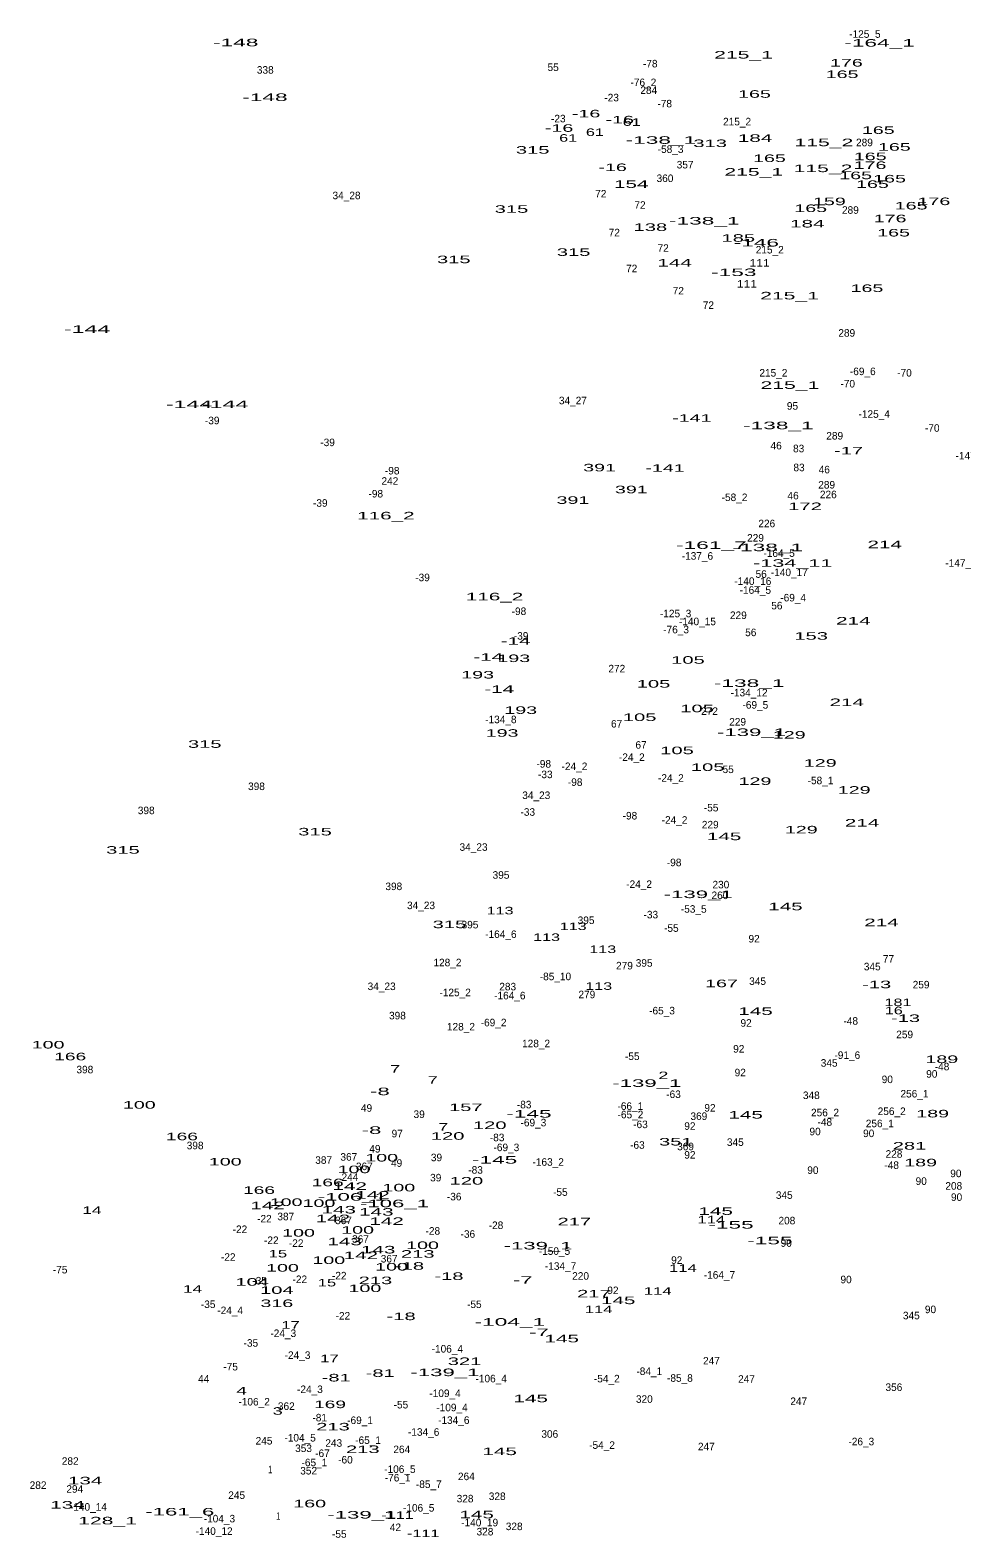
# Model space of a CAD drawing. Extents: x -662499 to -659675, y -1001682 to -998165.
# Drawn here: x -661282 to -660787, y -999947 to -999147 of the extents above; entities that cross this region are included whole.
import ezdxf
from ezdxf.enums import TextEntityAlignment as Align

# ---------------------------------------------------------------- set-up
doc = ezdxf.new("R2010")
doc.units = 0
doc.header["$LTSCALE"] = 1.6
doc.layers.add('24', color=7, linetype='Continuous')

msp = doc.modelspace()

# ---------------------------------------------------------------- texts
at = {"layer": '24'}
for s, p in [('-125_5', (-660838.646, -999150.64)), ('-78', (-660952.591, -999166.37)), ('338', (-661156.977, -999169.7)), ('55', (-661004.147, -999168.29)), ('-76_2', (-660956.234, -999176.31)), ('284', (-660953.381, -999180.47)), ('-23', (-660973.105, -999184.39)), ('-78', (-660944.931, -999187.61)), ('-23', (-661001.405, -999195.54)), ('215_2', (-660906.499, -999197.15)), ('-58_3', (-660941.792, -999211.8)), ('289', (-660838.873, -999208.24)), ('357', (-660934.083, -999220.04)), ('360', (-660944.767, -999227.26)), ('34_28', (-661113.83, -999236.38)), ('72', (-660978.853, -999235.47)), ('72', (-660958.043, -999241.48)), ('289', (-660846.343, -999244.12)), ('72', (-660971.693, -999256.1)), ('72', (-660945.743, -999264.33)), ('215_2', (-660889.149, -999265.21)), ('72', (-660962.443, -999275.17)), ('72', (-660937.703, -999287)), ('72', (-660921.733, -999294.65)), ('289', (-660848.283, -999309.41)), ('215_2', (-660887.209, -999330.6)), ('-69_6', (-660839.768, -999329.84)), ('-70', (-660817.614, -999330.58)), ('-70', (-660847.754, -999336.4)), ('34_27', (-660993.655, -999345.31)), ('95', (-660877.093, -999348.19)), ('-39', (-661185.15, -999355.93)), ('-125_4', (-660833.68, -999352.5)), ('289', (-660854.673, -999364.04)), ('-70', (-660802.874, -999359.93)), ('-39', (-661123.89, -999367.56)), ('46', (-660885.767, -999369.29)), ('83', (-660873.807, -999370.81)), ('-147_2', (-660782.176, -999374.64)), ('-98', (-661089.59, -999382.6)), ('83', (-660873.607, -999380.88)), ('46', (-660860.207, -999381.99)), ('242', (-661090.821, -999388.08)), ('289', (-660858.943, -999390.07)), ('-98', (-661098.31, -999394.82)), ('-58_2', (-660907.842, -999396.74)), ('46', (-660876.767, -999395.84)), ('226', (-660858.063, -999395.23)), ('-39', (-661127.77, -999399.76)), ('226', (-660890.723, -999410.65)), ('229', (-660896.713, -999418.28)), ('-137_6', (-660927.547, -999427.88)), ('-164_5', (-660884.196, -999426.4)), ('56', (-660893.703, -999437.51)), ('-140_17', (-660878.753, -999436.59)), ('-147_2', (-660787.606, -999431.65)), ('-39', (-661073.48, -999439.32)), ('-140_16', (-660898.133, -999441.28)), ('-164_5', (-660896.806, -999445.99)), ('56', (-660885.373, -999454.27)), ('-69_4', (-660876.718, -999450.05)), ('-98', (-661022.31, -999457.27)), ('-125_3', (-660939.126, -999458.47)), ('-140_15', (-660927.537, -999462.69)), ('229', (-660905.823, -999459.39)), ('-39', (-661021.14, -999470.35)), ('-76_3', (-660938.874, -999466.98)), ('56', (-660899.223, -999468.5)), ('272', (-660970.353, -999487.74)), ('-134_12', (-660900.123, -999500.47)), ('272', (-660921.133, -999510.34)), ('-69_5', (-660896.793, -999507)), ('-134_8', (-661031.9, -999514.73)), ('67', (-660970.448, -999517.03)), ('229', (-660906.213, -999515.99)), ('-24_2', (-660962.387, -999534.79)), ('67', (-660957.478, -999528.26)), ('-98', (-661009.13, -999538.33)), ('-24_2', (-660992.827, -999539.64)), ('-55', (-660912.115, -999541.24)), ('398', (-661161.643, -999550.26)), ('-33', (-661008.315, -999543.93)), ('-98', (-660992.46, -999548.03)), ('-24_2', (-660941.647, -999545.84)), ('-58_1', (-660862.196, -999547.15)), ('34_23', (-661013.1, -999555.01)), ('398', (-661220.183, -999563.06)), ('-33', (-661017.615, -999563.91)), ('-98', (-660963.38, -999565.87)), ('-55', (-660920.265, -999561.6)), ('-24_2', (-660939.707, -999568.15)), ('229', (-660920.753, -999570.63)), ('34_23', (-661046.4, -999582.52)), ('-98', (-660939.92, -999590.7)), ('395', (-661031.833, -999597.36)), ('398', (-661088.743, -999603.4)), ('-24_2', (-660958.517, -999602.26)), ('230', (-660915.101, -999602.48)), ('34_23', (-661074.28, -999613.51)), ('260', (-660915.607, -999608.16)), ('395', (-660986.653, -999621.41)), ('-33', (-660952.285, -999618.41)), ('-53_5', (-660929.502, -999615.42)), ('395', (-661048.303, -999623.74)), ('-164_6', (-661031.901, -999628.82)), ('-55', (-660941.395, -999625.56)), ('92', (-660897.463, -999631.22)), ('128_2', (-661060.259, -999643.87)), ('279', (-660966.288, -999645.52)), ('395', (-660955.833, -999644.1)), ('345', (-660834.741, -999646.01)), ('77', (-660826.149, -999641.95)), ('-85_10', (-661002.92, -999651.27)), ('345', (-660895.611, -999653.76)), ('34_23', (-661095.2, -999656.51)), ('-125_2', (-661056.176, -999659.76)), ('-164_6', (-661027.151, -999661.4)), ('283', (-661028.267, -999656.66)), ('279', (-660986.248, -999660.84)), ('259', (-660808.803, -999655.61)), ('-65_3', (-660946.348, -999669.42)), ('398', (-661086.803, -999672.05)), ('128_2', (-661053.099, -999677.96)), ('-69_2', (-661035.753, -999675.75)), ('92', (-660901.723, -999675.97)), ('-48', (-660846.149, -999674.9)), ('128_2', (-661013.209, -999686.87)), ('259', (-660817.533, -999682.08)), ('-55', (-660962.135, -999693.66)), ('92', (-660905.593, -999689.72)), ('-91_6', (-660847.967, -999693.07)), ('398', (-661252.753, -999700.72)), ('92', (-660904.823, -999702.31)), ('345', (-660857.621, -999697.21)), ('90', (-660803.127, -999703.03)), ('-48', (-660797.689, -999699.14)), ('90', (-660826.747, -999705.93)), ('-83', (-661019.545, -999719.33)), ('-63', (-660940.24, -999713.84)), ('348', (-660867.081, -999714.39)), ('256_1', (-660812.314, -999713.56)), ('49', (-661103.227, -999721.14)), ('39', (-661075.283, -999724.45)), ('-66_1', (-660963.157, -999720.15)), ('-65_2', (-660963.108, -999724.61)), ('369', (-660926.788, -999725.5)), ('92', (-660920.893, -999721.05)), ('256_2', (-660859.8, -999723.55)), ('256_2', (-660824.42, -999722.87)), ('97', (-661086.928, -999734.72)), ('-69_3', (-661014.623, -999728.89)), ('-63', (-660957.78, -999729.84)), ('92', (-660931.543, -999730.73)), ('90', (-660865.087, -999733.63)), ('-48', (-660859.919, -999728.62)), ('90', (-660836.627, -999734.6)), ('256_1', (-660830.734, -999729.36)), ('398', (-661194.213, -999741.06)), ('49', (-661098.777, -999742.83)), ('-83', (-661033.895, -999736.79)), ('-69_3', (-661028.963, -999742.07)), ('-63', (-660959.43, -999740.8)), ('369', (-660933.858, -999741.6)), ('345', (-660907.441, -999739.28)), ('387', (-661125.983, -999748.8)), ('367', (-661112.628, -999747.12)), ('49', (-661087.247, -999750.38)), ('39', (-661066.083, -999747.41)), ('-163_2', (-661006.792, -999749.83)), ('92', (-660931.543, -999746.04)), ('228', (-660823.187, -999745.57)), ('244', (-661112.026, -999757.84)), ('367', (-661104.388, -999752.15)), ('39', (-661066.473, -999758.14)), ('-83', (-661045.325, -999754.05)), ('90', (-660866.247, -999754.17)), ('-48', (-660824.439, -999751.51)), ('90', (-660790.347, -999755.91)), ('-55', (-661000.325, -999765.81)), ('345', (-660881.461, -999767.4)), ('90', (-660808.737, -999759.98)), ('208', (-660791.461, -999762.53)), ('-36', (-661056.69, -999768.21)), ('90', (-660789.957, -999768.5)), ('-22', (-661157.445, -999779.95)), ('387', (-661146.093, -999778.77)), ('367', (-661115.438, -999780.85)), ('-28', (-661034.485, -999783.43)), ('208', (-660880.051, -999780.96)), ('-22', (-661170.435, -999785.57)), ('-22', (-661153.765, -999791.39)), ('367', (-661106.428, -999790.74)), ('-28', (-661068.025, -999786.44)), ('-36', (-661049.42, -999788.09)), ('-22', (-661140.575, -999792.94)), ('-150_5', (-661003.43, -999797.15)), ('90', (-660880.387, -999792.88)), ('-75', (-661265.871, -999807.03)), ('-22', (-661176.635, -999800.31)), ('367', (-661091.208, -999801.21)), ('-134_7', (-661000.206, -999805.1)), ('92', (-660938.513, -999801.94)), ('-35', (-661159.975, -999812.89)), ('-22', (-661138.635, -999812.14)), ('-22', (-661117.705, -999810.2)), ('220', (-660989.571, -999810.36)), ('-164_7', (-660915.852, -999809.8)), ('90', (-660848.627, -999812.25)), ('92', (-660972.403, -999818.01)), ('-35', (-661187.305, -999825.4)), ('-24_4', (-661175.601, -999828.65)), ('-22', (-661115.765, -999831.53)), ('-55', (-661045.985, -999825.41)), ('345', (-660814.001, -999831.38)), ('90', (-660803.817, -999828.13)), ('-35', (-661164.625, -999845.96)), ('-24_3', (-661147.417, -999840.8)), ('-24_3', (-661139.857, -999852.43)), ('-106_4', (-661060.31, -999849.07)), ('247', (-660920.107, -999855.4)), ('-75', (-661175.371, -999858.56)), ('-84_1', (-660953.11, -999860.98)), ('44', (-661189.646, -999864.99)), ('-24_3', (-661133.267, -999870.57)), ('-106_4', (-661037.04, -999864.87)), ('-54_2', (-660975.667, -999864.91)), ('-85_8', (-660936.842, -999864.58)), ('247', (-660901.497, -999865.1)), ('356', (-660823.253, -999869.45)), ('-106_2', (-661162.896, -999877.18)), ('362', (-661145.813, -999879.53)), ('-55', (-661084.955, -999878.74)), ('-109_4', (-661061.53, -999872.68)), ('320', (-660955.741, -999875.75)), ('247', (-660873.767, -999876.93)), ('-81', (-661128.071, -999885.63)), ('-69_1', (-661106.657, -999887.02)), ('-109_4', (-661057.84, -999880.25)), ('-134_6', (-661056.906, -999886.96)), ('-134_6', (-661072.896, -999893.26)), ('306', (-661005.937, -999894.32)), ('245', (-661157.631, -999897.92)), ('-104_5', (-661138.484, -999896.33)), ('353', (-661136.657, -999901.9)), ('243', (-661120.631, -999899.11)), ('-65_1', (-661102.392, -999897.61)), ('264', (-661084.527, -999902.49)), ('-54_2', (-660978.187, -999900.21)), ('247', (-660922.817, -999900.98)), ('-26_3', (-660840.538, -999898.32)), ('282', (-661260.537, -999908.7)), ('-65_1', (-661130.882, -999909.44)), ('-67', (-661126.615, -999904.55)), ('-60', (-661114.414, -999908)), ('352', (-661133.947, -999913.83)), ('-106_5', (-661085.516, -999913.01)), ('-76_1', (-661086.697, -999917.54)), ('264', (-661050.217, -999916.84)), ('282', (-661277.597, -999921.5)), ('294', (-661258.117, -999923.53)), ('245', (-661172.171, -999926.82)), ('-85_7', (-661070.158, -999921.01)), ('328', (-661033.837, -999927.39)), ('-140_14', (-661250.851, -999933.05)), ('-106_5', (-661075.526, -999933.54)), ('328', (-661050.897, -999928.65)), ('-104_3', (-661181.324, -999939.28)), ('-140_19', (-661043.153, -999941.35)), ('328', (-661024.827, -999943.39)), ('-140_12', (-661184.127, -999945.9)), ('-55', (-661117.675, -999947.43)), ('42', (-661087.881, -999943.9)), ('328', (-661040.337, -999946.21))]:
    msp.add_text(s, height=4, dxfattribs=at).set_placement(p, align=Align.CENTER)
for s, width, p in [('-148', 2.25, (-661172.666, -999155.13)), ('-164_1', 2.25, (-660830.858, -999155.34)), ('215_1', 2.1, (-660903.065, -999161.66)), ('176', 1.95, (-660848.467, -999165.91)), ('165', 1.95, (-660850.733, -999172.01)), ('165', 1.95, (-660897.253, -999182.49)), ('-148', 2.25, (-661157.166, -999184.22)), ('-16', 1.95, (-660986.625, -999192.92)), ('-16', 1.95, (-660968.785, -999196.12)), ('61', 1.6, (-660962.433, -999197.41)), ('-16', 1.95, (-661000.965, -999200.58)), ('61', 1.6, (-660996.173, -999205.84)), ('61', 1.6, (-660981.983, -999202.79)), ('184', 2.05, (-660896.953, -999205.91)), ('165', 1.95, (-660831.533, -999201.69)), ('315', 2, (-661015.007, -999212.19)), ('-138_1', 2.25, (-660946.957, -999206.95)), ('313', 2, (-660920.807, -999208.68)), ('115_2', 2.1, (-660860.405, -999208.23)), ('165', 1.95, (-660823.003, -999210.61)), ('-16', 1.95, (-660972.565, -999221.43)), ('165', 1.95, (-660889.313, -999216.62)), ('115_2', 2.1, (-660860.885, -999221.99)), ('176', 1.95, (-660835.917, -999220.31)), ('165', 1.95, (-660835.803, -999215.65)), ('154', 2.05, (-660962.703, -999230.37)), ('215_1', 2.1, (-660897.635, -999223.87)), ('165', 1.95, (-660843.553, -999225.74)), ('165', 1.95, (-660834.633, -999230.39)), ('165', 1.95, (-660825.533, -999227.48)), ('315', 2, (-661026.257, -999243.6)), ('165', 1.95, (-660867.403, -999243.19)), ('159', 1.95, (-660857.493, -999239.55)), ('165', 1.95, (-660814.083, -999241.83)), ('176', 1.95, (-660801.997, -999239.51)), ('138', 2, (-660952.527, -999253.23)), ('-138_1', 2.25, (-660923.927, -999249.83)), ('184', 2.05, (-660869.223, -999251.39)), ('176', 1.95, (-660825.257, -999248.63)), ('185', 2, (-660905.857, -999258.98)), ('-146', 2.25, (-660896.281, -999261.49)), ('165', 1.95, (-660823.393, -999256.18)), ('315', 2, (-661056.887, -999270.37)), ('315', 2, (-660993.297, -999266.49)), ('144', 2.05, (-660939.669, -999272.14)), ('-153', 2.25, (-660908.241, -999277.2)), ('111', 1.2, (-660894.51, -999272.21)), ('111', 1.2, (-660901.24, -999283.35)), ('165', 1.95, (-660837.543, -999285.66)), ('215_1', 2.1, (-660878.635, -999289.61)), ('-144', 2.3, (-661251.542, -999307.39)), ('215_1', 2.1, (-660878.445, -999337.13)), ('-144', 2.3, (-661197.452, -999347.34)), ('-144', 2.3, (-661178.262, -999347.34)), ('-141', 1.95, (-660930.522, -999354.61)), ('-138_1', 2.25, (-660884.577, -999358.55)), ('-17', 2, (-660847.305, -999371.95)), ('391', 1.95, (-660979.503, -999380.96)), ('-141', 1.95, (-660944.762, -999381.18)), ('391', 1.95, (-660993.653, -999398.22)), ('391', 1.95, (-660962.633, -999392.6)), ('116_2', 2.05, (-661092.95, -999406.47)), ('172', 2, (-660870.413, -999401.52)), ('-161_7', 2.25, (-660920.157, -999422.15)), ('214', 2.05, (-660828.123, -999421.78)), ('-138_1', 2.25, (-660890.197, -999423.36)), ('-134_11', 2.15, (-660876.939, -999431.65)), ('116_2', 2.05, (-661035.25, -999449.47)), ('214', 2.05, (-660844.793, -999462.32)), ('153', 2, (-660867.167, -999470.38)), ('-14', 2.05, (-661024.066, -999473.04)), ('-14', 2.05, (-661038.606, -999481.57)), ('193', 1.95, (-661025.043, -999482.26)), ('105', 2, (-660932.564, -999483.15)), ('193', 1.95, (-661044.233, -999490.99)), ('-14', 2.05, (-661032.796, -999498.64)), ('105', 2, (-660950.854, -999495.83)), ('-138_1', 2.25, (-660900.087, -999495.43)), ('193', 1.95, (-661021.363, -999509.8)), ('105', 2, (-660927.724, -999508.91)), ('214', 2.05, (-660848.283, -999505.64)), ('105', 2, (-660958.214, -999513.56)), ('193', 1.95, (-661031.253, -999521.92)), ('-139_1', 2.2, (-660898.843, -999521.53)), ('129', 1.95, (-660878.803, -999522.93)), ('315', 2, (-661189.107, -999527.81)), ('105', 2, (-660938.374, -999531.19)), ('105', 2, (-660922.104, -999540.1)), ('129', 1.95, (-660862.343, -999537.85)), ('129', 1.95, (-660897.003, -999547.53)), ('129', 1.95, (-660844.333, -999552.18)), ('315', 2, (-661130.557, -999574.35)), ('129', 1.95, (-660872.413, -999573.29)), ('214', 2.05, (-660840.143, -999569.62)), ('145', 2.05, (-660913.393, -999576.87)), ('315', 2, (-661232.527, -999584.05)), ('-139_1', 2.2, (-660927.143, -999607.64)), ('145', 2.05, (-660880.823, -999614.1)), ('113', 1.6, (-661032.324, -999616.28)), ('214', 2.05, (-660829.863, -999622.56)), ('315', 2, (-661059.217, -999623.61)), ('113', 1.6, (-661007.634, -999630.42)), ('113', 1.6, (-660993.504, -999624.61)), ('113', 1.6, (-660977.814, -999636.81)), ('167', 1.95, (-660914.777, -999654.98)), ('113', 1.6, (-660979.944, -999656.38)), ('-13', 2, (-660832.401, -999655.51)), ('145', 2.05, (-660896.723, -999669.71)), ('181', 1.6, (-660821.074, -999665.02)), ('16', 1.6, (-660823.303, -999669.35)), ('-13', 2, (-660817.081, -999673.45)), ('100', 1.95, (-661272.27, -999687.53)), ('166', 1.9, (-661260.527, -999693.8)), ('189', 1.95, (-660797.813, -999695.24)), ('7', 1.8, (-661087.996, -999700.35)), ('7', 1.8, (-661068.046, -999706.26)), ('-139_1', 2.2, (-660954.423, -999707.92)), ('2', 1.8, (-660945.661, -999703.81)), ('-8', 2.2, (-661096.124, -999712.33)), ('100', 1.95, (-661223.86, -999719.49)), ('157', 2, (-661050.513, -999720.77)), ('-145', 2.25, (-661017.006, -999724.24)), ('145', 2.05, (-660901.953, -999724.76)), ('189', 1.95, (-660802.663, -999724.14)), ('-8', 2.2, (-661100.584, -999732.89)), ('7', 1.8, (-661062.436, -999731.15)), ('120', 2, (-661037.804, -999730.3)), ('166', 1.9, (-661201.207, -999736.27)), ('120', 2, (-661060.164, -999736.01)), ('351', 2, (-660939.017, -999739.08)), ('281', 2, (-660814.957, -999741.25)), ('100', 1.95, (-661178.24, -999749.69)), ('100', 1.95, (-661095.17, -999747.56)), ('-145', 2.25, (-661035.236, -999748.68)), ('189', 1.95, (-660809.053, -999750.13)), ('100', 1.95, (-661109.89, -999753.76)), ('166', 1.9, (-661160.297, -999764.78)), ('166', 1.9, (-661123.857, -999760.71)), ('142', 2.05, (-661112.153, -999762.66)), ('142', 2.05, (-661100.033, -999767.31)), ('100', 1.95, (-661086.07, -999763.45)), ('120', 2, (-661050.194, -999759.84)), ('14', 1.7, (-661249.023, -999775.44)), ('142', 2.05, (-661155.753, -999772.94)), ('100', 1.95, (-661145.91, -999771.19)), ('100', 1.95, (-661128.48, -999771.68)), ('-106_1', 2.2, (-661110.769, -999768.36)), ('143', 2.05, (-661117.963, -999775.17)), ('-106_1', 2.2, (-661088.379, -999771.86)), ('142', 2.05, (-661121.073, -999779.82)), ('143', 2.05, (-661098.003, -999776.33)), ('142', 2.05, (-661092.573, -999781.28)), ('217', 2, (-660992.893, -999781.47)), ('114', 1.65, (-660920.159, -999780.41)), ('145', 2.05, (-660917.853, -999775.93)), ('-155', 2.25, (-660909.731, -999783.2)), ('100', 1.95, (-661139.32, -999787.46)), ('100', 1.95, (-661107.95, -999785.92)), ('15', 1.65, (-661150.277, -999798.53)), ('143', 2.05, (-661114.863, -999792.04)), ('142', 2.05, (-661106.243, -999799.41)), ('143', 2.05, (-661097.033, -999796.4)), ('213', 2, (-661076.027, -999798.66)), ('100', 1.95, (-661073.49, -999794.05)), ('-139_1', 2.2, (-661012.153, -999794.28)), ('-155', 2.25, (-660889.081, -999791.54)), ('100', 1.95, (-661147.84, -999806.06)), ('100', 1.95, (-661123.25, -999801.99)), ('100', 1.95, (-661089.95, -999805.48)), ('-18', 2, (-661080.391, -999805.06)), ('114', 1.65, (-660935.259, -999806.18)), ('104', 2, (-661163.919, -999813.53)), ('15', 1.65, (-661124.237, -999813.93)), ('213', 2, (-661098.517, -999812.72)), ('-18', 2, (-661059.451, -999810.49)), ('-7', 2.2, (-661020.279, -999812.5)), ('14', 1.7, (-661195.583, -999817.28)), ('104', 2, (-661150.849, -999817.88)), ('100', 1.95, (-661104.08, -999816.91)), ('217', 2, (-660982.523, -999819.77)), ('145', 2.05, (-660969.613, -999823.34)), ('114', 1.65, (-660948.619, -999818.38)), ('316', 1.95, (-661150.843, -999824.87)), ('114', 1.65, (-660979.989, -999828.07)), ('17', 1.65, (-661143.513, -999836.36)), ('-18', 2, (-661084.841, -999831.82)), ('-104_1', 2.25, (-661027.139, -999834.79)), ('-7', 2.2, (-661011.659, -999840.33)), ('145', 2.05, (-660999.583, -999843.64)), ('17', 1.65, (-661122.893, -999854.18)), ('-81', 2, (-661095.941, -999861.97)), ('-139_1', 2.2, (-661061.593, -999861.57)), ('321', 2, (-661051.177, -999855.67)), ('4', 1.9, (-661169.537, -999871.34)), ('-81', 2, (-661119.301, -999864.4)), ('169', 1.9, (-661122.597, -999878.58)), ('145', 2.05, (-661016.063, -999875.45)), ('3', 1.8, (-661150.361, -999882.09)), ('213', 2, (-661121.007, -999890.42)), ('213', 2, (-661105.207, -999902.44)), ('145', 2.05, (-661032.543, -999903.53)), ('134', 2.05, (-661252.613, -999919.06)), ('1', 0.65, (-661154.357, -999913.19)), ('134', 2.05, (-661262.013, -999931.96)), ('-161_6', 2.2, (-661202.347, -999935.61)), ('160', 1.95, (-661133.399, -999931.28)), ('128_1', 2.1, (-661240.705, -999940.34)), ('1', 0.65, (-661150.097, -999937.89)), ('-139_1', 2.2, (-661105.713, -999937.24)), ('-111', 1.6, (-661086.783, -999937.43)), ('145', 2.05, (-661044.763, -999937.09)), ('-111', 1.6, (-661073.113, -999947.12))]:
    msp.add_text(s, height=4, dxfattribs=dict(at, width=width)).set_placement(p, align=Align.CENTER)

doc.saveas('drawing.dxf')
